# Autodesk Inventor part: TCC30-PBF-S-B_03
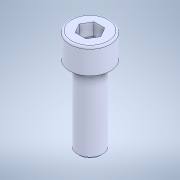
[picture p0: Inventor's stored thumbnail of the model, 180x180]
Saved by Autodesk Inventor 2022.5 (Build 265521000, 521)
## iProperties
Created: 2023-09
Part Number: TCC30-PBF-S-B_03
Material: 一般
Document SubType Name: Modeling
Designer: ImaoCorp
Density: 1 g/cm^3
Appearance: 既定
Author: ImaoCorp
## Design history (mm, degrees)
feature "TCC30-PBF-S-B_03"
node "ソリッド1"
